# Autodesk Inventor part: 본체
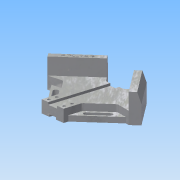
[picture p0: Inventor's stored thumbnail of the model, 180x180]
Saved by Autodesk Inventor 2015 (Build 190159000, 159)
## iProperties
Created: 2020-05
Part Number: 본체
Material: 알루미늄 6061
Document SubType Name: Modeling
Designer: 105687
Density: 2.7 g/cm^3
Appearance: 알루미늄 - 평지
Mass: 569.845 g
Surface Area: 406.639 cm^2
Volume: 211.054 cm^3
Author: 105687
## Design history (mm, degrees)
sketch "스케치1"
  geometry: L1 (20, 64.853)-(84.853, 0); L2 (84.853, 0)-(35.355, -49.497); L3 (-35.355, -49.497)-(-84.853, 0); L4 (-84.853, 0)-(-20, 64.853); L5 (35.355, -49.497)-(16.005, -30.147); L6 (63.963, 84.853)-(-70.167, 84.853); L7 (20, 64.853)-(-20, 64.853); L8 (0, 64.853)-(0, -30.147); L9 (16.005, -30.147)-(-16.005, -30.147); L10 (-35.355, -49.497)-(-16.005, -30.147); 4 further points
  constraints: 20 end point, 2 horizontal, 2 point on line, 1 coincident, 1 horizontal alignment, 1 midpoint, 1 parallel, 1 vertical, 5 other
  dimensions: "d3" = 64.85281 distance from line of L7 point (0, 0); "d4" = 95 distance of L8.start L8.end; "d6" = 120 distance between parallel lines of L4 L2; "d7" = 10 distance from line of point (0, 0) L10; "d8" = 90 deg angle of L10 L3; "d9" = 90 deg angle of L2 L5; "d10" = 10 distance from line of point (0, 0) L5; "d11" = 30.14719 distance from line of point (0, 0) L9; "d20" = 15 distance from line of point (74.246, 10.607) L2; "d25" = 80 distance from line of L2 point (28.284, 56.569)
extrude "돌출1" new body sketch "스케치1" distance "d12" = 18; taper "d13" = 0 deg
sketch "스케치3"
  geometry: L1 (36.005, 18)-(3.995, 18) reference; L2 (12, 18)-(28, 18); L3 (28, 18)-(28, 14.5); L4 (28, 14.5)-(12, 14.5); L5 (12, 14.5)-(12, 18); L6 (14, 0)-(26, 0); L7 (26, 0)-(26, 3); L8 (26, 3)-(14, 3); L9 (14, 3)-(14, 0); L10 (0, 0)-(40, 0) reference; 7 further points
  constraints: 16 end point, 6 midpoint, 4 parallel, 2 horizontal, 2 perpendicular, 2 vertical alignment, 1 coincident, 1 point on line
  dimensions: "d26" = 16 distance between parallel lines of L3 L5; "d27" = 3.5 distance between parallel lines of L1 L4; "d28" = 12 distance between parallel lines of L7 L9; "d29" = 3 distance between parallel lines of L6 L8
extrude "돌출3" cut sketch "스케치3" stored distance "d30" = 18; taper "d31" = 0 deg
sketch "스케치4"
  geometry: L1 (-74.246, -10.607)-(-49.497, -7.071); L2 (-84.853, 0)-(-20, -64.853) reference; L3 (-74.246, -10.607)-(-20, -64.853); L4 (-35.355, 49.497)-(-84.853, 0) reference; L5 (-20, -64.853)-(-20, -36.569); L6 (-49.497, -7.071)-(-63.64, -21.213); L7 (-49.497, -7.071)-(-20, -36.569); L8 (-49.497, -7.071)-(0.503, -7.071); 1 further point
  constraints: 12 end point, 3 point on line, 1 collinear, 1 horizontal, 1 perpendicular, 1 vertical
  dimensions: "d32" = 15 distance from line of L1.start L4; "d33" = 30 distance from line of L1.end L4; "d36" = 20 horizontal distance of L3.end point (0, 0); "d43" = 20 distance from line of L1.end L2; "d45" = 45 deg angle of L7 L8
extrude "돌출4" cut sketch "스케치4" stored distance "d38" = 18; taper "d39" = 0 deg
sketch "스케치5"
  geometry: L1 (8, -64.853)-(-8, -64.853) reference; C1 r 2.25 at (-14, -46.853); C2 r 2.25 at (-14, -58.853); 1 further point
  constraints: 2 centre point, 1 vertical alignment
  dimensions: "d40" = 4.5 diameter of C1; "d41" = 4.5 diameter of C2; "d42" = 14 horizontal distance of C2.centre point (0, 0); "d46" = 6 distance from line of C2.centre L1; "d47" = 12 distance of C1.centre C2.centre
extrude "돌출5" cut sketch "스케치5" distance "d48" = 10; taper "d49" = 0 deg
sketch "스케치6"
  geometry: C1 r 2.25 at (0, 0) reference; C2 r 4 at (0, 0); C3 r 2.25 at (0, -12) reference; C4 r 4 at (0, -12); 1 further point
  constraints: 2 centre point, 2 coincident
  dimensions: "d50" = 8 diameter of C2; "d51" = 8 diameter of C4
extrude "돌출6" cut sketch "스케치6" stored distance "d52" = 10; taper "d53" = 0 deg
sketch "스케치7"
  geometry: L1 (0, 18)-(15, 18); L2 (15, 18)-(15, 42); L3 (15, 42)-(5, 42); L4 (0, 27)-(0, 18); L5 (0, 0)-(15, 0) reference; L6 (0, 27)-(5, 42); 1 further point
  constraints: 10 end point, 2 parallel, 1 horizontal, 1 perpendicular
  dimensions: "d55" = 42 distance between parallel lines of L5 L3; "d63" = 5 distance from line of L3.end L4; "d64" = 15 distance between parallel lines of L2 L4; "d65" = 15 distance from line of L4.start L3
extrude "돌출7" join sketch "스케치7" distance "d60" = 70; taper "d61" = 0 deg
sketch "스케치8"
  geometry: L1 (0, 18)-(-15, 18); L2 (-15, 18)-(-15, 42); L3 (-15, 42)-(-5, 42); L4 (0, 27)-(0, 18); L5 (-15, 0)-(0, 0) reference; L6 (0, 27)-(-5, 42); 1 further point
  constraints: 10 end point, 2 parallel, 1 horizontal, 1 perpendicular
  dimensions: "d67" = 42 distance between parallel lines of L5 L3; "d69" = 5 distance from line of L4 L3.end; "d70" = 15 vertical distance of L4.start L3.end; "d71" = 15 distance between parallel lines of L4 L2
extrude "돌출8" join sketch "스케치8" distance "d72" = 70; taper "d73" = 0 deg
node "작업 평면1"
sketch "스케치9"
  geometry: L1 (6, -30.147)-(6, 64.853) reference; L2 (6, 64.853)-(20, 64.853) reference; L3 (20, 64.853)-(20, 36.569) reference; L4 (20, 36.569)-(49.497, 7.071) reference; L5 (49.497, 7.071)-(74.246, 10.607) reference; L6 (74.246, 10.607)-(84.853, 0) reference; L7 (84.853, 0)-(35.355, -49.497) reference; L8 (35.355, -49.497)-(16.005, -30.147) reference; L9 (16.005, -30.147)-(6, -30.147) reference; L10 (-6, 64.853)-(-6, -30.147) reference; L11 (-6, -30.147)-(-16.005, -30.147) reference; L12 (-16.005, -30.147)-(-35.355, -49.497) reference; L13 (-35.355, -49.497)-(-84.853, 0) reference; L14 (-84.853, 0)-(-74.246, 10.607) reference; L15 (-74.246, 10.607)-(-49.497, 7.071) reference; L16 (-49.497, 7.071)-(-20, 36.569) reference; L17 (-20, 36.569)-(-20, 64.853) reference; L18 (-20, 64.853)-(-6, 64.853) reference; L19 (74.246, 10.607)-(20, 64.853); L20 (68.059, 9.723)-(20, 57.782); L21 (68.059, 9.723)-(49.497, 7.071); L22 (49.497, 7.071)-(20, 36.569); L23 (20, 36.569)-(20, 57.782); C1 r 4 at (-14, 58.853) reference; C2 r 4 at (-14, 46.853) reference; C3 r 4 at (14, 46.853) reference; C4 r 4 at (14, 58.853) reference; 1 further point
  constraints: 10 end point, 2 collinear, 2 point on line, 1 parallel
  dimensions: "d76" = 15 distance between parallel lines of L20 L4
extrude "돌출9" join sketch "스케치9" distance "d77" = 8; taper "d78" = 0 deg
sketch "스케치10"
  geometry: L1 (-84.853, 0)-(-35.355, 49.497) reference; L2 (-74.246, -10.607)-(-81.317, -3.536) reference; L3 (-52.326, -21.213)-(-32.527, -41.012); L4 (-46.492, -15.745)-(-26.871, -35.354); L5 (-68.059, -9.723)-(-20, -57.782) reference; A1 r 4 centre (-49.497, -18.385) between (-46.492, -15.745) and (-52.326, -21.213); A2 r 4 centre (-29.698, -38.184) between (-32.527, -41.012) and (-26.871, -35.354); 1 further point
  constraints: 4 end point, 4 point on circle, 2 centre point, 1 tangent
  dimensions: "d79" = 8 diameter of A1; "d80" = 8 diameter of A2; "d81" = 38 distance from line of A1.centre L1; "d82" = 66 distance from line of A2.centre L1; "d83" = 12 distance from line of A1.centre L2; "d84" = 12 distance from line of L2 A2.centre; "d85" = 0.017318 deg angle of L4 L3; "d86" = 0.017318 deg angle of L5 L4; "d87" = 4 distance from line of L3 A1.centre
extrude "돌출10" cut sketch "스케치10" stored distance "d88" = 8; taper "d89" = 0 deg
sketch "스케치11"
  geometry: L1 (26.871, 35.354)-(46.492, 15.745) reference; L2 (52.326, 21.213)-(32.527, 41.012) reference; L3 (6, -30.147)-(6, 64.853) reference; L4 (6, 64.853)-(20, 64.853) reference; L5 (20, 64.853)-(20, 57.782) reference; L6 (20, 57.782)-(68.059, 9.723) reference; L7 (68.059, 9.723)-(74.246, 10.607) reference; L8 (74.246, 10.607)-(84.853, 0) reference; L9 (84.853, 0)-(35.355, -49.497) reference; L10 (35.355, -49.497)-(16.005, -30.147) reference; L11 (16.005, -30.147)-(6, -30.147) reference; L12 (-6, 64.853)-(-6, -30.147) reference; L13 (-6, -30.147)-(-16.005, -30.147) reference; L14 (-16.005, -30.147)-(-35.355, -49.497) reference; L15 (-35.355, -49.497)-(-84.853, 0) reference; L16 (-84.853, 0)-(-74.246, 10.607) reference; L17 (-74.246, 10.607)-(-49.497, 7.071) reference; L18 (-49.497, 7.071)-(-20, 36.569) reference; L19 (-20, 36.569)-(-20, 64.853) reference; L20 (-20, 64.853)-(-6, 64.853) reference; L21 (-20, 64.853)-(-74.246, 10.607); L22 (-20, 57.782)-(-20, 36.569); L23 (-20, 36.569)-(-49.497, 7.071); L24 (-49.497, 7.071)-(-68.059, 9.723); L25 (-20, 57.782)-(-68.059, 9.723); C1 r 4 at (-14, 58.853) reference; C2 r 4 at (-14, 46.853) reference; C3 r 4 at (14, 46.853) reference; C4 r 4 at (14, 58.853) reference; A1 r 4 centre (49.497, 18.385) between (46.492, 15.745) and (52.326, 21.213) reference; A2 r 4 centre (29.698, 38.184) between (32.527, 41.012) and (26.871, 35.354) reference; 1 further point
  constraints: 10 end point, 2 collinear, 2 point on line, 1 parallel
  dimensions: "d91" = 15 distance between parallel lines of L18 L25
extrude "돌출11" join sketch "스케치11" distance "d92" = 8; taper "d93" = 0 deg
sketch "스케치12"
  geometry: L1 (0, 0)-(70, 0) reference; L2 (70, 10)-(70, 0) reference; 2 further points
  constraints: 1 other
  dimensions: "d94" = 5 distance from line of point (35, 5) L1; "d95" = 35 distance from line of point (35, 5) L2
feature "엠보싱1" sketch "스케치12" dims "d3" = 64.85281, "d4" = 95, "d6" = 120, "d7" = 10, "d8" = 90 deg, "d9" = 90 deg, "d10" = 10, "d11" = 30.14719, "d20" = 15, "d25" = 80, "d26" = 16, "d27" = 3.5, "d96" = 0.5, "d97" = 0
fillet "모깎기1" dims "d98" = 5
node "솔리드1"
mirror "대칭1"
mirror "대칭2"
mirror "대칭3"
node "절단 모서리 투영1"
node "절단 모서리 투영2"
other parameters: "d74" = 0, "d75" = 5, "d90" = 5
